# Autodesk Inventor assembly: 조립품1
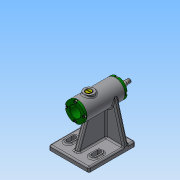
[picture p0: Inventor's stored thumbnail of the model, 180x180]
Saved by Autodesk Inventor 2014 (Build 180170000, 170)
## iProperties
Created: 2019-10
Part Number: 조립품1
Document SubType Name: Assembly
Designer: NET
Author: NET
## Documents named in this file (8)
- C:\Users\NET\Desktop\491004V1041\조립품1.iam
- C:\Users\NET\Desktop\491004V1041\부품1.ipt
- C:\Users\NET\Desktop\491004V1041\나사.ipt
- C:\Users\NET\Desktop\491004V1041\커버.ipt
- C:\Users\NET\Desktop\491004V1041\슬리브.ipt
- C:\Users\NET\Desktop\491004V1041\나사축.ipt
- C:\Users\NET\Desktop\491004V1041\부시.ipt
- C:\Users\NET\Desktop\491004V1041\볼트 M3.ipt
